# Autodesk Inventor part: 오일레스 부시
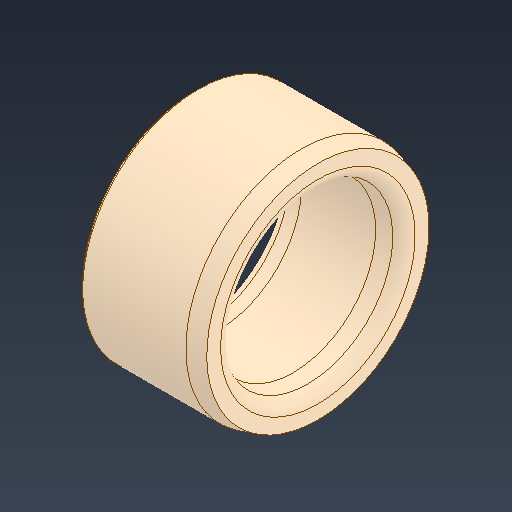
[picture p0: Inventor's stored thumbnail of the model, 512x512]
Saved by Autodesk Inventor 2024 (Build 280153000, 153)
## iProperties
Created: 2024-05
Part Number: 오일레스 부시
Material: 구리, 합금
Document SubType Name: Modeling
Designer: kh_501
Density: 8.92 g/cm^3
Appearance: 기본값
Author: jhkim
Sending System: Autodesk Inventor 2025
Preprocessor: ST-DEVELOPER v20
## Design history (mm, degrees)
node "오일레스 부시1"
node "솔리드2"
node "솔리드1"
